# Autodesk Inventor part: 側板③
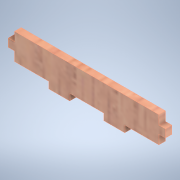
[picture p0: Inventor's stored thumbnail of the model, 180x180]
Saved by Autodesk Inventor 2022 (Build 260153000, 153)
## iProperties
Created: 2024-11
Part Number: 側板③
Material: 木 (オーク)
Document SubType Name: Modeling
Designer: shimizu
Density: 0.76 g/cm^3
Appearance: ホワイト オーク材 - ナチュラル 標準の光沢
Author: shimizu
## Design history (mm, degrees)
sketch "スケッチ1"
  geometry: L1 (-25.358, 1.343)-(29.642, 1.343); L2 (-4.358, -8.657)-(-4.358, -11.157); L3 (-4.358, -11.157)-(-12.358, -11.157); L4 (-12.358, -11.157)-(-12.358, -8.657); L5 (16.642, -8.657)-(16.642, -11.157); L6 (16.642, -11.157)-(8.642, -11.157); L7 (8.642, -11.157)-(8.642, -8.657); L8 (-25.358, -2.157)-(-27.858, -2.157); L9 (-27.858, -2.157)-(-27.858, -5.157); L10 (-27.858, -5.157)-(-25.358, -5.157); L11 (29.642, -2.157)-(32.142, -2.157); L12 (32.142, -2.157)-(32.142, -5.157); L13 (32.142, -5.157)-(29.642, -5.157); L14 (-25.358, -8.657)-(-25.358, -5.157); L15 (-25.358, -2.157)-(-25.358, 1.343); L16 (29.642, 1.343)-(29.642, -2.157); L17 (29.642, -5.157)-(29.642, -8.657); L18 (29.642, -8.657)-(16.642, -8.657); L19 (8.642, -8.657)-(-4.358, -8.657); L20 (-12.358, -8.657)-(-25.358, -8.657); 1 further point
  constraints: 40 end point, 11 parallel, 4 perpendicular, 3 horizontal
  dimensions: "d16" = 13 distance of L17.end L5.start; "d17" = 13 distance of L4.end L14.start; "d18" = 8 distance of L5.end L6.end; "d19" = 8 distance of L2.end L3.end; "d20" = 13 distance of L7.end L2.start; "d21" = 55 distance between parallel lines of L16 L15; "d22" = 60 distance between parallel lines of L12 L9
extrude "押し出し1" new body sketch "スケッチ1" distance "d14" = 2.5; taper "d15" = 0 deg
node "ソリッド1"
